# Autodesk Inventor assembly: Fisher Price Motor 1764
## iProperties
Shininess: 64.0
Angle Display Precision: 2
Document Length Units: 11272
Document Angle Units: 11279
Document Time Units: 11290
Document Mass Units: 11286
Document Length Units Precision: 3
Document Angle Units Precision: 2
Category: Motors
Created: 2001-12
Document SubType Name: Assembly
Project: FIRST
Vendor: FisherPrice
Part Number: Fisher Price Motor 1764
Description: FisherPrice Motor and Gearbox
Density: 0.0
Volumn: 0.0
Area: 0.0
PropertySet Name: Model Information
Control State: 0
Master: False
Checked Out: False
Author: Autodesk, Inc.
Title: FisherPrice Motor and Gearbox
